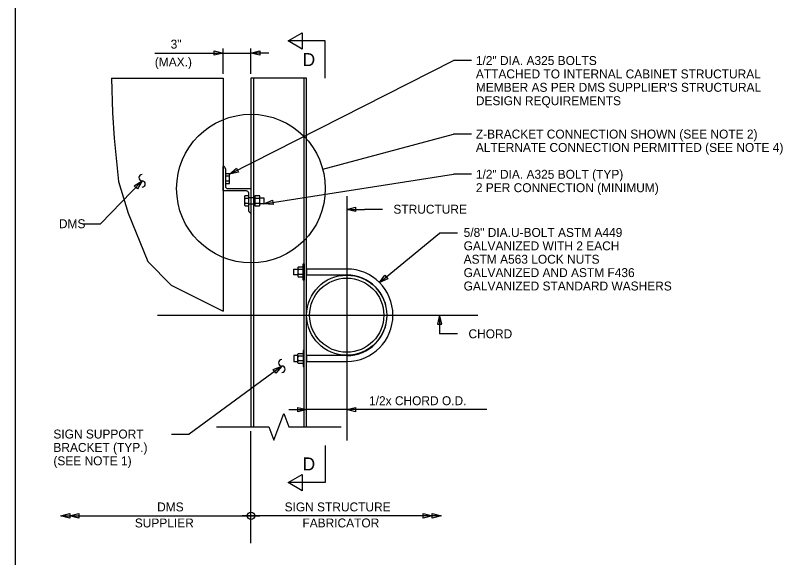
# Model space of a CAD drawing. Extents: x 3831399 to 3833095, y 499014 to 500202.
# Drawn here: x 3832280.2 to 3832538.2, y 499201.4 to 499383.6 of the extents above; entities that cross this region are included whole.
import ezdxf

# ---------------------------------------------------------------- set-up
doc = ezdxf.new("R2010")
doc.units = 0
for name, color, linetype in [('0-ANCHOR', 7, 'Continuous'), ('2', 7, 'Continuous'), ('CNTR', 7, 'Continuous'), ('Default', 7, 'Continuous'), ('DIM TXT', 7, 'Continuous'), ('sign', 7, 'Continuous'), ('structure', 7, 'Continuous')]:
    doc.layers.add(name, color=color, linetype=linetype)

msp = doc.modelspace()

# ---------------------------------------------------------------- linework, layer by layer
at = {"layer": '0-ANCHOR'}
for p, q in [((3832352, 499330.4), (3832350.82, 499330.4)), ((3832350.82, 499330.4), (3832350.82, 499327.08)), ((3832352, 499329.57), (3832350.82, 499329.57)), ((3832352.19, 499327.27), (3832352.19, 499330.21)), ((3832352, 499327.91), (3832350.82, 499327.91)), ((3832350.82, 499327.08), (3832352, 499327.08)), ((3832357.27, 499322.79), (3832357.27, 499319.85)), ((3832358.63, 499322.98), (3832357.45, 499322.98)), ((3832357.45, 499322.15), (3832358.63, 499322.15)), ((3832357.45, 499320.49), (3832358.63, 499320.49)), ((3832358.63, 499319.66), (3832358.63, 499322.98)), ((3832360.66, 499322.3), (3832358.63, 499322.3)), ((3832362.23, 499322.98), (3832360.66, 499322.98)), ((3832360.66, 499322.98), (3832360.66, 499319.66)), ((3832360.66, 499320.34), (3832360.66, 499322.3)), ((3832360.66, 499322.15), (3832362.23, 499322.15)), ((3832360.66, 499320.49), (3832362.23, 499320.49)), ((3832362.42, 499319.85), (3832362.42, 499322.79)), ((3832362.42, 499322.3), (3832363.77, 499322.3)), ((3832363.77, 499322.3), (3832363.77, 499320.34)), ((3832357.45, 499319.66), (3832358.63, 499319.66)), ((3832358.63, 499320.34), (3832360.66, 499320.34)), ((3832360.66, 499319.66), (3832362.23, 499319.66)), ((3832363.77, 499320.34), (3832362.42, 499320.34))]:
    msp.add_line(p, q, dxfattribs=at)
for centre, start, end in [((3832352, 499330.21), 360, 90), ((3832352, 499329.76), 270, 0), ((3832352, 499327.72), 360, 90), ((3832352, 499327.27), 270, 0), ((3832357.45, 499322.79), 90, 180), ((3832357.45, 499322.34), 180, 270), ((3832357.45, 499320.3), 90, 180), ((3832362.23, 499322.79), 360, 90), ((3832362.23, 499322.34), 270, 0), ((3832362.23, 499320.3), 360, 90), ((3832357.45, 499319.85), 180, 270), ((3832362.23, 499319.85), 270, 0)]:
    msp.add_arc(centre, 0.187, start, end, dxfattribs=at)
for centre, major_axis, start_param, end_param in [((3832352, 499329.05), (0, 0.518), 4.712389, 6.283185), ((3832352, 499328.43), (0, -0.518), 0, 1.570796), ((3832357.45, 499321.63), (0, 0.518), 0, 1.570796), ((3832357.45, 499321.01), (0, -0.518), 4.712389, 6.283185), ((3832362.23, 499321.63), (0, 0.518), 4.712389, 6.283185), ((3832362.23, 499321.01), (0, -0.518), 0, 1.570796)]:
    msp.add_ellipse(centre, major_axis=major_axis, ratio=0.362172, start_param=start_param, end_param=end_param, dxfattribs=at)
at = {"layer": '2'}
msp.add_line((3832280.16, 499029.03), (3832280.16, 499593.03), dxfattribs=at)
at = {"layer": 'CNTR'}
for p, q in [((3832391.61, 499322.89), (3832391.61, 499240.76)), ((3832327.92, 499282.84), (3832435.73, 499282.84))]:
    msp.add_line(p, q, dxfattribs=at)
at = {"layer": 'Default'}
for p, q in [((3832371.88, 499375.03), (3832376.65, 499377.78)), ((3832376.65, 499377.78), (3832376.65, 499372.28)), ((3832376.65, 499372.28), (3832371.88, 499375.03)), ((3832371.88, 499226.6), (3832376.65, 499229.35)), ((3832376.65, 499229.35), (3832376.65, 499223.85)), ((3832376.65, 499223.85), (3832371.88, 499226.6))]:
    msp.add_line(p, q, dxfattribs=at)
at = {"layer": 'DIM TXT'}
for p, q in [((3832384.38, 499375.03), (3832371.88, 499375.03)), ((3832384.38, 499362.53), (3832384.38, 499375.03)), ((3832350.04, 499364.03), (3832350.04, 499372.47)), ((3832359.41, 499364.03), (3832359.41, 499372.47)), ((3832327.07, 499370.97), (3832350.04, 499370.97)), ((3832350.04, 499370.97), (3832359.41, 499370.97)), ((3832365.41, 499370.97), (3832359.41, 499370.97)), ((3832352.19, 499330.21), (3832427.55, 499368.45)), ((3832433.55, 499368.45), (3832427.55, 499368.45)), ((3832383.56, 499331.91), (3832427.55, 499343.74)), ((3832433.55, 499343.74), (3832427.55, 499343.74)), ((3832363.77, 499320.34), (3832427.55, 499330.21)), ((3832433.55, 499330.21), (3832427.55, 499330.21)), ((3832322.78, 499328.02), (3832308.85, 499313.6)), ((3832391.61, 499318.41), (3832397.61, 499318.41)), ((3832403.61, 499318.41), (3832397.61, 499318.41)), ((3832302.85, 499313.6), (3832308.85, 499313.6)), ((3832402.61, 499293.8), (3832422.86, 499310.48)), ((3832428.86, 499310.48), (3832422.86, 499310.48)), ((3832422.86, 499282.84), (3832422.86, 499276.59)), ((3832428.86, 499276.59), (3832422.86, 499276.59)), ((3832369.78, 499265.76), (3832338.63, 499242.9)), ((3832372.13, 499251.1), (3832378.13, 499251.1)), ((3832378.13, 499246.84), (3832378.13, 499252.6)), ((3832391.61, 499251.1), (3832378.13, 499251.1)), ((3832438.72, 499251.1), (3832391.61, 499251.1)), ((3832368.77, 499245.34), (3832370.44, 499249.85)), ((3832370.44, 499249.85), (3832372.11, 499245.34)), ((3832391.61, 499249.6), (3832391.61, 499249.6)), ((3832347.76, 499245.34), (3832365.44, 499245.34)), ((3832359.41, 499206.2), (3832359.41, 499243.84)), ((3832365.44, 499245.34), (3832367.11, 499240.83)), ((3832367.11, 499240.83), (3832368.77, 499245.34)), ((3832372.11, 499245.34), (3832389.79, 499245.34)), ((3832332.63, 499242.9), (3832338.63, 499242.9)), ((3832384.38, 499239.09), (3832384.38, 499226.6)), ((3832384.38, 499226.6), (3832371.88, 499226.6)), ((3832295.48, 499215.4), (3832359.41, 499215.4)), ((3832298.48, 499215.4), (3832362.41, 499215.4)), ((3832420.34, 499215.4), (3832356.41, 499215.4)), ((3832423.34, 499215.4), (3832359.41, 499215.4))]:
    msp.add_line(p, q, dxfattribs=at)
for points in [[(3832347.04, 499371.72), (3832350.04, 499370.97), (3832347.04, 499370.22)], [(3832362.41, 499370.22), (3832359.41, 499370.97), (3832362.41, 499371.72)], [(3832355.2, 499330.9), (3832352.19, 499330.21), (3832354.52, 499332.24)], [(3832320.15, 499326.38), (3832322.78, 499328.02), (3832321.23, 499325.34)], [(3832366.85, 499320.06), (3832363.77, 499320.34), (3832366.62, 499321.54)], [(3832394.61, 499317.66), (3832391.61, 499318.41), (3832394.61, 499319.16)], [(3832405.4, 499295.13), (3832402.61, 499293.8), (3832404.45, 499296.29)], [(3832423.61, 499279.84), (3832422.86, 499282.84), (3832422.11, 499279.84)], [(3832366.91, 499264.59), (3832369.78, 499265.76), (3832367.8, 499263.38)], [(3832375.13, 499251.85), (3832378.13, 499251.1), (3832375.13, 499250.35)], [(3832394.61, 499250.35), (3832391.61, 499251.1), (3832394.61, 499251.85)], [(3832298.48, 499214.65), (3832295.48, 499215.4), (3832298.48, 499216.15)], [(3832301.48, 499214.65), (3832298.48, 499215.4), (3832301.48, 499216.15)], [(3832417.34, 499216.15), (3832420.34, 499215.4), (3832417.34, 499214.65)], [(3832420.34, 499216.15), (3832423.34, 499215.4), (3832420.34, 499214.65)]]:
    msp.add_lwpolyline(points, close=True, dxfattribs=at)
for centre, radius in [((3832359.41, 499325.42), 25), ((3832359.41, 499215.4), 1.25)]:
    msp.add_circle(centre, radius, dxfattribs=at)
for centre, start, end in [((3832322.78, 499329.09), 90, 270), ((3832322.78, 499326.94), 270, 90), ((3832369.78, 499266.84), 90, 270), ((3832369.78, 499264.69), 270, 90)]:
    msp.add_arc(centre, 1.08, start, end, dxfattribs=at)
at = {"layer": 'sign'}
for p, q in [((3832312.54, 499362.53), (3832350.04, 499362.53)), ((3832312.54, 499362.53), (3832312.88, 499350.91)), ((3832350.04, 499362.53), (3832350.04, 499284.25)), ((3832312.88, 499350.91), (3832313.45, 499342.41)), ((3832313.45, 499342.41), (3832314.83, 499327.8)), ((3832350.04, 499324.64), (3832350.04, 499332.84)), ((3832350.82, 499332.06), (3832350.82, 499326.2)), ((3832314.83, 499327.8), (3832318.06, 499317.19)), ((3832357.85, 499324.64), (3832350.04, 499324.64)), ((3832351.6, 499325.42), (3832359.41, 499325.42)), ((3832358.63, 499318), (3832358.63, 499323.86)), ((3832359.41, 499325.42), (3832359.41, 499317.22)), ((3832318.06, 499317.19), (3832324.67, 499300.9)), ((3832324.67, 499300.9), (3832332.51, 499292.9)), ((3832376.93, 499294.66), (3832376.93, 499300.13)), ((3832376.93, 499300.13), (3832377.32, 499300.13)), ((3832377.32, 499300.13), (3832377.32, 499294.66)), ((3832373.82, 499296.42), (3832373.82, 499298.37)), ((3832373.82, 499298.37), (3832375.17, 499298.37)), ((3832375.17, 499298.87), (3832375.17, 499295.92)), ((3832376.93, 499299.05), (3832375.36, 499299.05)), ((3832376.93, 499298.22), (3832375.36, 499298.22)), ((3832376.93, 499295.73), (3832376.93, 499299.05)), ((3832391.61, 499298.37), (3832378.13, 499298.37)), ((3832378.13, 499298.37), (3832378.13, 499296.42)), ((3832375.17, 499296.42), (3832373.82, 499296.42)), ((3832376.93, 499296.56), (3832375.36, 499296.56)), ((3832375.36, 499295.73), (3832376.93, 499295.73)), ((3832377.32, 499294.66), (3832376.93, 499294.66)), ((3832378.13, 499296.42), (3832391.61, 499296.42)), ((3832332.51, 499292.9), (3832350.04, 499284.25)), ((3832375.17, 499269.27), (3832373.82, 499269.27)), ((3832373.82, 499269.27), (3832373.82, 499267.32)), ((3832375.17, 499266.82), (3832375.17, 499269.77)), ((3832375.36, 499269.95), (3832376.93, 499269.95)), ((3832376.93, 499269.12), (3832375.36, 499269.12)), ((3832377.32, 499271.03), (3832376.93, 499271.03)), ((3832376.93, 499271.03), (3832376.93, 499265.56)), ((3832376.93, 499269.95), (3832376.93, 499266.63)), ((3832377.32, 499265.56), (3832377.32, 499271.03)), ((3832391.61, 499269.27), (3832378.13, 499269.27)), ((3832378.13, 499269.27), (3832378.13, 499267.32)), ((3832373.82, 499267.32), (3832375.17, 499267.32)), ((3832376.93, 499267.46), (3832375.36, 499267.46)), ((3832376.93, 499266.63), (3832375.36, 499266.63)), ((3832378.13, 499267.32), (3832391.61, 499267.32)), ((3832376.93, 499265.56), (3832377.32, 499265.56))]:
    msp.add_line(p, q, dxfattribs=at)
for centre, radius, start, end in [((3832350.04, 499332.06), 0.781, 0, 90), ((3832351.6, 499326.2), 0.781, 180, 270), ((3832357.85, 499323.86), 0.781, 0, 90), ((3832359.41, 499318), 0.781, 180, 270), ((3832375.36, 499298.87), 0.187, 90, 180), ((3832375.36, 499298.41), 0.187, 180, 270), ((3832391.61, 499282.84), 15.53, 270, 90), ((3832375.36, 499296.38), 0.187, 90, 180), ((3832375.36, 499295.92), 0.187, 180, 270), ((3832391.61, 499282.84), 13.57, 270, 90), ((3832375.36, 499269.77), 0.187, 90, 180), ((3832375.36, 499269.31), 0.187, 180, 270), ((3832375.36, 499267.28), 0.187, 90, 180), ((3832375.36, 499266.82), 0.187, 180, 270)]:
    msp.add_arc(centre, radius, start, end, dxfattribs=at)
for centre, major_axis, start_param, end_param in [((3832375.36, 499297.71), (0, 0.518), 0, 1.570796), ((3832375.36, 499297.08), (0, -0.518), 4.712389, 6.283185), ((3832375.36, 499268.61), (0, 0.518), 0, 1.570796), ((3832375.36, 499267.98), (0, -0.518), 4.712389, 6.283185)]:
    msp.add_ellipse(centre, major_axis=major_axis, ratio=0.362172, start_param=start_param, end_param=end_param, dxfattribs=at)
at = {"layer": 'structure'}
for p, q in [((3832378.13, 499362.53), (3832359.41, 499362.53)), ((3832359.41, 499362.53), (3832359.41, 499245.34)), ((3832377.32, 499362.53), (3832360.23, 499362.53)), ((3832360.23, 499362.53), (3832360.23, 499245.34)), ((3832377.32, 499245.34), (3832377.32, 499362.53)), ((3832378.13, 499245.34), (3832378.13, 499362.53))]:
    msp.add_line(p, q, dxfattribs=at)
for radius in [13.48, 12.47]:
    msp.add_circle((3832391.61, 499282.84), radius, dxfattribs=at)

# ---------------------------------------------------------------- texts
at = {"layer": 'DIM TXT'}
for s, height, p in [('3"', 3, (3832332.39, 499372.47)), ('(MAX.)', 3, (3832327.07, 499366.47)), ('D', 4.37, (3832376.77, 499366.59)), ('1/2" DIA. A325 BOLTS', 2.9999, (3832435.04, 499366.95)), ('ATTACHED TO INTERNAL CABINET STRUCTURAL', 2.9999, (3832435.04, 499362.45)), ("MEMBER AS PER DMS SUPPLIER'S STRUCTURAL", 2.9999, (3832435.04, 499357.95)), ('DESIGN REQUIREMENTS', 2.9999, (3832435.04, 499353.45)), ('Z-BRACKET CONNECTION SHOWN (SEE NOTE 2)', 2.9999, (3832435.04, 499342.24)), ('ALTERNATE CONNECTION PERMITTED (SEE NOTE 4)', 2.9999, (3832435.04, 499337.74)), ('1/2" DIA. A325 BOLT (TYP)', 2.9999, (3832435.04, 499328.71)), ('2 PER CONNECTION (MINIMUM)', 2.9999, (3832435.04, 499324.21)), ('  STRUCTURE', 2.9999, (3832405.08, 499316.97)), ('DMS', 3, (3832294.81, 499312.1)), ('5/8" DIA.U-BOLT ASTM A449', 2.9999, (3832430.93, 499309.16)), ('GALVANIZED WITH 2 EACH', 2.9999, (3832430.93, 499304.66)), ('ASTM A563 LOCK NUTS', 2.9999, (3832430.93, 499300.16)), ('GALVANIZED AND ASTM F436', 2.9999, (3832430.93, 499295.66)), ('GALVANIZED STANDARD WASHERS', 2.9999, (3832430.93, 499291.16)), ('  CHORD', 3, (3832430.33, 499275.09)), ('1/2x CHORD O.D.', 2.9999, (3832399.11, 499252.6)), ('SIGN SUPPORT', 2.9999, (3832292.96, 499241.4)), ('BRACKET (TYP.)', 2.9999, (3832292.96, 499236.9)), ('(SEE NOTE 1)', 2.9999, (3832292.96, 499232.4)), ('D', 4.37, (3832376.77, 499230.66)), ('DMS', 3, (3832327.85, 499216.9)), ('SIGN STRUCTURE', 2.9999, (3832370.72, 499216.9)), ('SUPPLIER', 3, (3832320.34, 499211.51)), ('FABRICATOR', 3, (3832376.71, 499211.51))]:
    msp.add_text(s, height=height, dxfattribs=at).set_placement(p)

doc.saveas('drawing.dxf')
